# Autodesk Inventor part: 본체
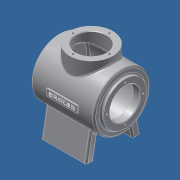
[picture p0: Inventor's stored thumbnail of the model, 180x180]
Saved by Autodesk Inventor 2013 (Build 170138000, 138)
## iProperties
Created: 2015-01
Part Number: 본체
Material: 알루미늄 6061
Document SubType Name: Modeling
Designer: hanacad21
Density: 2.71 g/cm^3
Mass: 1021.13 g
Surface Area: 1060.32 cm^2
Volume: 376.801 cm^3
Author: hanacad21
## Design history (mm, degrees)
node "작업 평면1"
node "작업 평면2"
sketch "스케치1"
  geometry: C1 r 38 at (0, 0); 1 further point
  constraints: 1 centre point, 1 coincident
  dimensions: "d2" = 76 diameter of C1
extrude "돌출1" new body sketch "스케치1" stored distance "d4" = 10; taper "d5" = 0 deg
node "작업 평면3"
node "작업 평면4"
sketch "스케치2"
  geometry: C1 r 50 at (0, 0); 1 further point
  constraints: 1 centre point, 1 coincident
  dimensions: "d8" = 100 diameter of C1
extrude "돌출2" join sketch "스케치2" stored distance "d9" = 10; taper "d10" = 0 deg
node "작업 평면5"
node "작업 평면6"
sketch "스케치3"
  geometry: C1 r 45 at (0, 0); 1 further point
  constraints: 1 centre point, 1 coincident
  dimensions: "d13" = 90 diameter of C1
extrude "돌출3" cut sketch "스케치3" stored distance "d14" = 10; taper "d15" = 0 deg
node "작업 평면7"
node "작업 평면8"
sketch "스케치8"
  geometry: L1 (41.901, 27.282)-(80, 34); L2 (80, 34)-(80, 48); L3 (80, 48)-(30.865, 39.336); A1 r 50 centre (0, 0) between (30.865, 39.336) and (41.901, 27.282) reference; A2 r 50 centre (0, 0) between (41.901, 27.282) and (30.865, 39.336); 1 further point
  constraints: 6 end point, 4 point on circle, 1 centre point, 1 coincident, 1 concentric, 1 vertical
  dimensions: "d34" = 48 vertical distance of L2.end point (0, 0); "d35" = 80 distance from line of L2 point (0, 0); "d36" = 14 distance of L1.end L2.end; "d37" = 80 deg angle of L1 L2; "d38" = 100 deg angle of L3 L2
extrude "돌출6" join sketch "스케치8" distance "d39" = 80; taper "d40" = 0 deg
hole "구멍2" diameter "d52" = 54; stored, may be unused: countersink angle "d56" = 90 deg, drill point angle "d58" = 0 deg; dims "d50" = 10, "d51" = 10, "d53" = 6, "d54" = 4, "d55" = 2, "d57" = 60
hole "구멍3" diameter "d61" = 54; stored, may be unused: countersink angle "d65" = 90 deg, drill point angle "d67" = 0 deg; dims "d59" = 10, "d60" = 10, "d62" = 6, "d63" = 4, "d64" = 2, "d66" = 60
sketch "스케치9"
  geometry: C1 r 27 at (0, 0) reference; 1 further point
  constraints: 1 vertical alignment
  dimensions: "d68" = 32 distance of C1.centre point (0, 32)
hole "구멍4" sketch "스케치9" at (0, 32) diameter "d69" = 3.242; stored, may be unused: countersink angle "d73" = 90 deg, drill point angle "d75" = 118 deg; dims "d70" = 8, "d71" = 4, "d72" = 2, "d74" = 10
sketch "스케치10"
  geometry: C1 r 27 at (0, 0) reference; 1 further point
  constraints: 1 vertical alignment
  dimensions: "d79" = 32 distance of C1.centre point (0, 32)
hole "구멍5" sketch "스케치10" at (0, 32) diameter "d80" = 3.242; stored, may be unused: countersink angle "d84" = 90 deg, drill point angle "d86" = 118 deg; dims "d81" = 8, "d82" = 4, "d83" = 2, "d85" = 10
node "작업 평면9"
sketch "스케치12"
  geometry: L1 (27, 6)-(-27, 6); L2 (-27, 6)-(-27, -6); L3 (-27, -6)-(27, -6); L4 (27, -6)-(27, 6); 3 further points
  constraints: 8 end point, 2 midpoint, 2 parallel, 1 horizontal, 1 horizontal alignment, 1 perpendicular, 1 vertical alignment
  dimensions: "d101" = 54 distance between parallel lines of L2 L4; "d103" = 12 distance between parallel lines of L3 L1
extrude "돌출7" join sketch "스케치12" stored distance "d104" = 4; taper "d105" = 0 deg
sketch "스케치13"
  geometry: 2 further points
  constraints: 1 coincident, 1 other
feature "엠보싱1" sketch "스케치13" dims "d106" = 0.5, "d107" = 0
fillet "모깎기1" dims "d108" = 3
fillet "모깎기2" dims "d109" = 3
fillet "모깎기3" dims "d110" = 3
fillet "모깎기4" dims "d111" = 3
fillet "모깎기5" dims "d112" = 3
chamfer "모따기1" distance "d113" = 1; stored, may be unused: second distance "d114" = 2, angle "d115" = 45 deg
fillet "모깎기7" dims "d117" = 3
node "작업 평면11"
sketch "스케치15"
  geometry: C1 r 38 at (0, 0); 1 further point
  constraints: 1 centre point, 1 coincident
  dimensions: "d119" = 76 diameter of C1
extrude "돌출8" join sketch "스케치15" stored distance "d121" = 4; taper "d122" = 0 deg
hole "구멍7" diameter "d125" = 54; stored, may be unused: countersink angle "d129" = 90 deg, drill point angle "d131" = 0 deg; dims "d123" = 10, "d124" = 10, "d126" = 8, "d127" = 4, "d128" = 2, "d130" = 62
sketch "스케치16"
  geometry: C1 r 27 at (0, 0) reference; 1 further point
  constraints: 1 vertical alignment
  dimensions: "d132" = 32 distance of point (0, 32) C1.centre
hole "구멍8" sketch "스케치16" at (0, 32) diameter "d133" = 3.242; stored, may be unused: countersink angle "d137" = 90 deg, drill point angle "d139" = 118 deg; dims "d134" = 8, "d135" = 4, "d136" = 2, "d138" = 10
chamfer "모따기2" distance "d143" = 1; stored, may be unused: second distance "d144" = 2, angle "d145" = 45 deg
fillet "모깎기8" dims "d146" = 3
fillet "모깎기9" dims "d147" = 3
node "솔리드1"
mirror "대칭2"
pattern_circular "원형 패턴1" dims angle "d77" = 360 deg
pattern_circular "원형 패턴2" dims angle "d88" = 360 deg
pattern_circular "원형 패턴4" dims angle "d141" = 360 deg
other parameters: "d1" = -62, "d6" = -5, "d7" = -5, "d11" = -8, "d12" = -7, "d16" = 68, "d33" = -21, "d118" = 62
